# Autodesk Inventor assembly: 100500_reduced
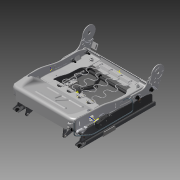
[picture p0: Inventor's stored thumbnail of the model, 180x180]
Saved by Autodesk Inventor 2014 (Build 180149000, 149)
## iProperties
Created: 2007-12
Part Number: 100500_reduced
Document SubType Name: Assembly
Designer: MM
Mass: 67948.6 g
Surface Area: 51487.2 cm^2
Volume: 67429.6 cm^3
Density: 1.0077 g/cm^3
Description: SUPER CAR DRIVER SEAT 1000
Component Category: Seat Assembly
Author: MM
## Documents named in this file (9)
- C:\Users\iTools\Desktop\tutorial files\Automotive\1000\100500.iam
- C:\Users\iTools\Desktop\tutorial files\Automotive\2000\202985.iam
- C:\Users\iTools\Desktop\tutorial files\Automotive\9000\900247.ipt
- C:\Users\iTools\Desktop\tutorial files\Automotive\9000\900100_MIR.ipt
- C:\Users\iTools\Desktop\tutorial files\Automotive\9000\900568.ipt
- C:\Users\iTools\Desktop\tutorial files\Automotive\9000\900575.ipt
- C:\Users\iTools\Desktop\tutorial files\Automotive\9000\900356.ipt
- C:\Users\iTools\Desktop\tutorial files\Automotive\9000\900420.ipt
- C:\Users\iTools\Desktop\tutorial files\Automotive\1000\100500\100500.Harness1.iam
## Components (10 placed, 8 different names)
1. 202985:1 [sub-assembly] — Mate:40, Mate:41, Mate:45, Flush:12, Flush:13, Mate:46, Flush:15, Flush:16, Flush:17, Mate:47, Mate:48, Flush:18, Flush:19, Insert:6, Angle:5, Insert:7, Angle:6
2. 900247:1 — Insert:7, Angle:6
3. 900100_MIR:1 — Mate:40, Mate:41, Mate:42, Mate:43, Mate:44
4. 900568:1 — Mate:42, Mate:43, Mate:44
5. 900575:1 — Mate:45, Flush:12, Flush:13
6. 900575:2 — Mate:46, Flush:15
7. 900575:3 — Flush:16, Flush:17, Mate:47
8. 900356:1 — Mate:48, Flush:18, Flush:19
9. 900420:1 — Insert:6, Angle:5
10. Harness1 [sub-assembly]
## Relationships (20: Mate 9, Flush 7, Insert 2, Angle 2)
- Mate:40: 202985:1 ↔ 900100_MIR:1
- Mate:41: 202985:1 ↔ 900100_MIR:1
- Mate:42: 900100_MIR:1 ↔ 900568:1
- Mate:43: 900100_MIR:1 ↔ 900568:1
- Mate:44: 900100_MIR:1 ↔ 900568:1
- Mate:45: 202985:1 ↔ 900575:1
- Flush:12: 202985:1 ↔ 900575:1
- Flush:13: 202985:1 ↔ 900575:1
- Mate:46: 202985:1 ↔ 900575:2
- Flush:15: 202985:1 ↔ 900575:2
- Flush:16: 202985:1 ↔ 900575:3
- Flush:17: 202985:1 ↔ 900575:3
- Mate:47: 202985:1 ↔ 900575:3
- Mate:48: 202985:1 ↔ 900356:1
- Flush:18: 202985:1 ↔ 900356:1
- Flush:19: 202985:1 ↔ 900356:1
- Insert:6: 202985:1 ↔ 900420:1
- Angle:5: 202985:1 ↔ 900420:1
- Insert:7: 202985:1 ↔ 900247:1
- Angle:6: 202985:1 ↔ 900247:1
